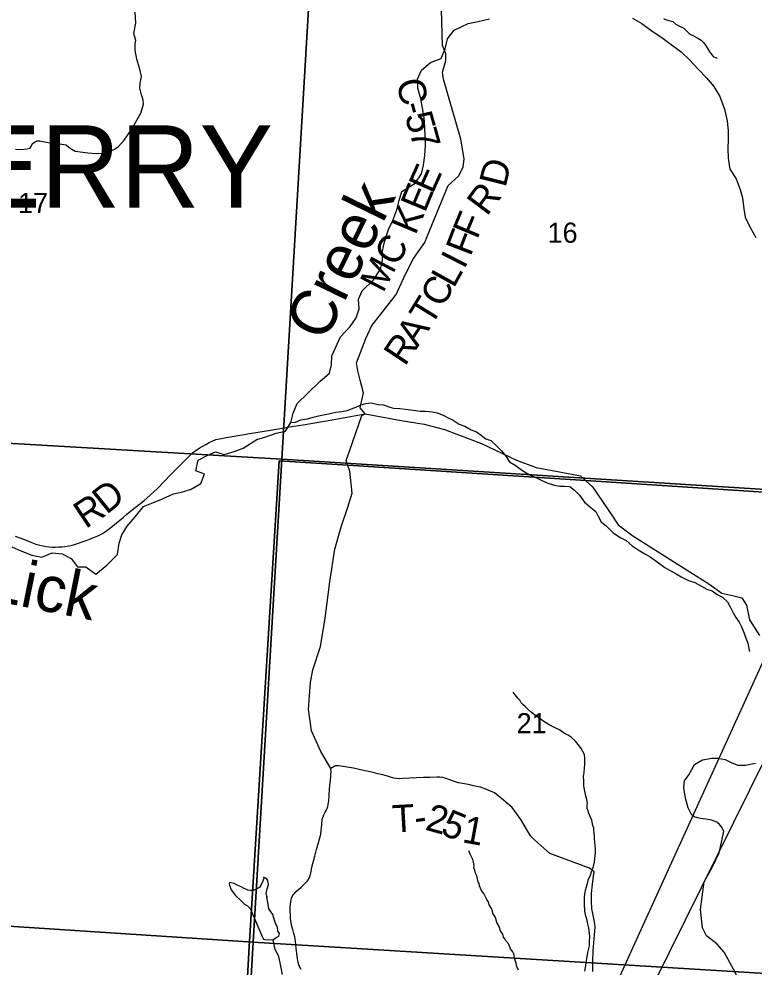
# Model space of a CAD drawing. Extents: x 0 to 45.4, y -2.2 to 22.
# Drawn here: x 4.467 to 5.991, y 17.183 to 19.147 of the extents above; entities that cross this region are included whole.
import ezdxf

# ---------------------------------------------------------------- set-up
doc = ezdxf.new("R2010")
doc.units = 0
for name, color, linetype in [('GM_X_Corporation', 7, 'Continuous'), ('GM_X_County_Road', 7, 'Continuous'), ('GM_X_County_Road_Text', 7, 'Continuous'), ('GM_X_Minor_Lake', 7, 'Continuous'), ('GM_X_Minor_River', 7, 'Continuous'), ('GM_X_Minor_River_Text', 7, 'Continuous'), ('GM_X_Section_Text', 7, 'Continuous'), ('GM_X_Township_Road', 7, 'Continuous'), ('GM_X_Township_Road_Text', 7, 'Continuous'), ('GM_X_Township_Text', 7, 'Continuous'), ('SH_Text', 7, 'Continuous')]:
    doc.layers.add(name, color=color, linetype=linetype)

msp = doc.modelspace()

# ---------------------------------------------------------------- linework, layer by layer
at = {"layer": 'GM_X_Corporation'}
for points in [[(5.073, 19.2613), (5.0121, 18.2353), (3.9206, 18.2985), (3.9891, 19.3268)], [(6.1827, 19.1954), (6.1142, 18.166), (5.0121, 18.2353), (5.073, 19.2613)], [(3.9206, 18.2985), (5.0121, 18.2353), (4.9524, 17.2347), (3.854, 17.3067)], [(5.0121, 18.2353), (6.1142, 18.166), (6.0488, 17.1677), (4.9524, 17.2347)], [(4.9524, 17.2347), (4.8941, 16.2254), (3.7867, 16.2913), (3.854, 17.3067)], [(6.0488, 17.1677), (5.9818, 16.1569), (4.8941, 16.2254), (4.9524, 17.2347)]]:
    msp.add_lwpolyline(points, close=True, dxfattribs=at)
for points in [[(6.1061, 18.1607), (5.642, 18.1908), (5.1488, 18.2228), (5.0067, 18.2321), (4.9442, 17.2251), (4.9098, 16.6105)], [(4.9098, 16.6105), (4.9442, 17.2251), (5.0067, 18.2321), (5.1488, 18.2228), (5.642, 18.1908), (6.1061, 18.1607)]]:
    msp.add_lwpolyline(points, dxfattribs=at)
at = {"layer": 'GM_X_County_Road'}
for points in [[(5.1851, 18.3294), (5.1744, 18.3414), (5.1816, 18.3726), (5.1744, 18.399), (5.1696, 18.4182), (5.1672, 18.435), (5.1864, 18.4854), (5.1984, 18.5118), (5.2176, 18.5357), (5.2488, 18.5765), (5.268, 18.6173), (5.2848, 18.6509), (5.2968, 18.6677), (5.3088, 18.6844), (5.3136, 18.6964), (5.3568, 18.802), (5.3784, 18.8212), (5.3879, 18.8403), (5.3903, 18.8571), (5.3832, 18.8979), (5.3472, 19.0226), (5.3448, 19.037), (5.352, 19.061), (5.352, 19.0754), (5.3448, 19.0921), (5.3422, 19.1916)], [(4.4597, 18.0756), (4.471, 18.0718), (4.4822, 18.0674), (4.4921, 18.063), (4.5019, 18.0589), (4.5108, 18.0569), (4.517, 18.0554), (4.5237, 18.0545), (4.5293, 18.0539), (4.5369, 18.0532), (4.5425, 18.0531), (4.5492, 18.0533), (4.5565, 18.0537), (4.5623, 18.0545), (4.5699, 18.0555), (4.5753, 18.0566), (4.5823, 18.0587), (4.5883, 18.0607), (4.596, 18.0633), (4.6021, 18.0653), (4.6085, 18.0675), (4.6122, 18.069), (4.6202, 18.0721), (4.6306, 18.0767), (4.6403, 18.0812), (4.6469, 18.0854), (4.6541, 18.0908), (4.6652, 18.1001), (4.6831, 18.1146), (4.6908, 18.1213), (4.702, 18.1304), (4.7261, 18.1487), (4.7392, 18.1603), (4.7549, 18.1752), (4.7812, 18.2028), (4.8018, 18.2233), (4.8115, 18.2329), (4.8195, 18.2407), (4.8279, 18.2487), (4.8338, 18.2535), (4.8406, 18.2582), (4.8545, 18.2657), (4.8618, 18.2695), (4.8755, 18.2757), (4.8869, 18.2782), (4.8969, 18.28), (4.9338, 18.2863), (4.9451, 18.2882), (4.9887, 18.2956), (5.0277, 18.3023), (5.0561, 18.3065), (5.1166, 18.3166), (5.1851, 18.3294), (5.2595, 18.3156), (5.3073, 18.3079), (5.3495, 18.2965), (5.426, 18.2677), (5.4988, 18.2333), (5.539, 18.218), (5.6022, 18.2065), (5.6309, 18.2008), (5.6422, 18.1903), (5.6558, 18.1778), (5.6882, 18.1304), (5.6945, 18.1211)], [(5.6945, 18.1211), (5.7094, 18.0993), (5.74, 18.0764), (5.897, 17.9768), (5.9238, 17.9577), (5.9487, 17.952), (5.9659, 17.9481), (5.9755, 17.9328), (5.9812, 17.9022), (6.0023, 17.8696)]]:
    msp.add_lwpolyline(points, dxfattribs=at)
at = {"layer": 'GM_X_Minor_Lake'}
for points in [[(4.9814, 17.328), (4.9795, 17.3348), (4.9818, 17.3451), (4.9844, 17.3538), (4.9829, 17.3625), (4.9803, 17.3663), (4.9739, 17.369), (4.9746, 17.3663), (4.972, 17.3599), (4.9689, 17.3519), (4.9655, 17.3481), (4.9614, 17.3459), (4.953, 17.3417), (4.9462, 17.3413), (4.9413, 17.3425), (4.9391, 17.344), (4.9326, 17.3467), (4.9281, 17.3489), (4.9209, 17.352), (4.913, 17.3558), (4.9073, 17.3577), (4.9035, 17.3581), (4.9028, 17.3554), (4.9039, 17.3524), (4.9069, 17.3433), (4.916, 17.3311), (4.9266, 17.3216), (4.9345, 17.3133), (4.9409, 17.3098), (4.9462, 17.3041), (4.9711, 17.2464), (4.9742, 17.2407), (4.9761, 17.2403), (4.9937, 17.2397)], [(4.9937, 17.2397), (5.0003, 17.2441), (5.0059, 17.2471), (5.0071, 17.2528), (5.004, 17.2574), (5.0033, 17.2657), (4.9999, 17.2722), (4.9965, 17.282), (4.9935, 17.2919), (4.9855, 17.3037), (4.981, 17.3291), (4.9814, 17.328)]]:
    msp.add_lwpolyline(points, dxfattribs=at)
at = {"layer": 'GM_X_Minor_River'}
for points in [[(4.4525, 18.0537), (4.4714, 18.0453), (4.4941, 18.0361), (4.5145, 18.0322), (4.5358, 18.0412), (4.557, 18.0389), (4.5751, 18.0297), (4.5887, 18.0122), (4.6061, 18.0121), (4.6265, 17.9969), (4.6493, 18.0158), (4.6713, 18.0377), (4.6752, 18.0612), (4.6806, 18.0787), (4.6913, 18.0961), (4.708, 18.1158), (4.7255, 18.137), (4.746, 18.1452), (4.765, 18.1528), (4.7877, 18.1633), (4.8067, 18.1678), (4.8241, 18.1731), (4.8439, 18.1851), (4.8515, 18.2041), (4.8341, 18.211), (4.8388, 18.233), (4.857, 18.2428), (4.8744, 18.2503), (4.8926, 18.2449), (4.9131, 18.2509), (4.932, 18.2577), (4.9601, 18.2758), (4.9791, 18.2818), (5.0003, 18.2893), (5.02, 18.2931), (5.0307, 18.3113), (5.0353, 18.3302), (5.0438, 18.3507), (5.0658, 18.3719), (5.0909, 18.3961), (5.1107, 18.4135), (5.1153, 18.4309), (5.1154, 18.4491), (5.1337, 18.4886), (5.1535, 18.5098), (5.1664, 18.5279), (5.1726, 18.5469), (5.1711, 18.5666), (5.1788, 18.5841), (5.2024, 18.6068), (5.2168, 18.6287), (5.2207, 18.6469), (5.2208, 18.6659), (5.2246, 18.6856), (5.2331, 18.7107), (5.2423, 18.7296), (5.2507, 18.7516), (5.2553, 18.7713), (5.2607, 18.7895), (5.2888, 18.8069), (5.3017, 18.8266), (5.3056, 18.844), (5.3087, 18.8645), (5.3096, 18.885), (5.3089, 18.904), (5.3082, 18.9222), (5.3068, 18.9427), (5.3038, 18.9625), (5.3001, 18.9815), (5.2941, 19.0035), (5.2935, 19.0225), (5.3019, 19.0414), (5.3201, 19.0573), (5.3421, 19.0656), (5.3505, 19.0853), (5.3552, 19.1058), (5.3696, 19.124), (5.3985, 19.1375), (5.4189, 19.142), (5.4424, 19.1472)], [(5.7393, 19.1485), (5.7582, 19.1378), (5.7794, 19.1218)], [(5.7794, 19.1218), (5.7998, 19.1088), (5.8194, 19.0944), (5.8398, 19.0791), (5.8571, 19.0623), (5.8745, 19.0441), (5.8926, 19.025), (5.9076, 19.0075), (5.9197, 18.9862), (5.9294, 18.9604), (5.9354, 18.9361), (5.9375, 18.9148), (5.9375, 18.8973), (5.9366, 18.8791), (5.9373, 18.8586), (5.941, 18.8358), (5.9538, 18.816), (5.962, 18.794), (5.9673, 18.7765), (5.9694, 18.7537), (5.9724, 18.7363), (5.9822, 18.7165), (5.9949, 18.6944)], [(5.0307, 18.3113), (5.0402, 18.3121), (5.0512, 18.3166), (5.0652, 18.3189), (5.0769, 18.3223), (5.0879, 18.3253), (5.1019, 18.3276), (5.1121, 18.3295), (5.1238, 18.3325), (5.1367, 18.334), (5.1476, 18.3359), (5.162, 18.3415), (5.1764, 18.3476), (5.1862, 18.3502), (5.1976, 18.3517), (5.2119, 18.3487), (5.2225, 18.3479), (5.2339, 18.3433), (5.2437, 18.3407), (5.2569, 18.3399), (5.2687, 18.3391), (5.2845, 18.3368), (5.2985, 18.3349), (5.3099, 18.3349), (5.3235, 18.3334), (5.3344, 18.3315), (5.3465, 18.3261), (5.3571, 18.3208), (5.3673, 18.3159), (5.3798, 18.3075), (5.3915, 18.3033), (5.4047, 18.2957), (5.4153, 18.2915), (5.4252, 18.2851), (5.435, 18.2771), (5.4452, 18.274), (5.4569, 18.263), (5.4675, 18.2528), (5.4766, 18.2414), (5.4841, 18.23), (5.4958, 18.2231), (5.506, 18.2152), (5.5174, 18.2076), (5.5287, 18.2015), (5.5389, 18.1969), (5.5495, 18.192), (5.5635, 18.1855), (5.5775, 18.1813), (5.5881, 18.179), (5.5983, 18.179), (5.6089, 18.1786), (5.6187, 18.1707), (5.6289, 18.1604), (5.6398, 18.146), (5.6527, 18.135), (5.6629, 18.127), (5.6678, 18.1171), (5.6742, 18.1053), (5.6852, 18.0962), (5.6988, 18.0826), (5.715, 18.0719), (5.726, 18.0666), (5.7385, 18.0559), (5.7509, 18.0472), (5.7645, 18.0388), (5.7755, 18.0331), (5.7929, 18.0202), (5.8061, 18.0111), (5.8159, 18.005), (5.8296, 17.9978), (5.8409, 17.991), (5.8549, 17.9841), (5.8681, 17.9799), (5.8821, 17.9719), (5.8931, 17.9662), (5.9044, 17.9624), (5.9142, 17.9548), (5.9252, 17.9491), (5.9358, 17.9396), (5.9411, 17.929), (5.9479, 17.9172), (5.9531, 17.9074), (5.9603, 17.8975), (5.9648, 17.8876), (5.9698, 17.8759), (5.9739, 17.8641), (5.9781, 17.8542), (5.9799, 17.8432), (5.9818, 17.8371)], [(5.5387, 17.7032), (5.5297, 17.7106), (5.5226, 17.7168), (5.5174, 17.7222), (5.5118, 17.7272), (5.5085, 17.7303), (5.5055, 17.7357), (5.5022, 17.7395), (5.4959, 17.7472), (5.4914, 17.7522)], [(5.64, 17.1744), (5.6425, 17.1865), (5.6426, 17.1926), (5.6434, 17.1967), (5.6459, 17.2085), (5.6464, 17.213), (5.6496, 17.2267), (5.6501, 17.2346), (5.6504, 17.2479), (5.6501, 17.2521), (5.6494, 17.2582), (5.6484, 17.2643), (5.6459, 17.275), (5.6453, 17.2803), (5.6424, 17.2887), (5.6403, 17.2987), (5.6404, 17.3025), (5.6397, 17.3097), (5.6392, 17.3207), (5.6393, 17.3283), (5.641, 17.3382), (5.6418, 17.3423), (5.6434, 17.3492), (5.6463, 17.3586), (5.6471, 17.3632), (5.6518, 17.3737), (5.6542, 17.3805), (5.6582, 17.3915), (5.6586, 17.3949), (5.6603, 17.4009), (5.6616, 17.4138), (5.6621, 17.4188), (5.6626, 17.4267), (5.6616, 17.4351), (5.6606, 17.4416), (5.66, 17.4492), (5.66, 17.4534), (5.6598, 17.4595), (5.6588, 17.4679), (5.6585, 17.4713), (5.657, 17.4762), (5.6553, 17.4835), (5.655, 17.4873), (5.652, 17.4934), (5.648, 17.503), (5.6473, 17.5068), (5.6452, 17.5118), (5.6453, 17.5186), (5.6454, 17.5228), (5.644, 17.5304), (5.6415, 17.54), (5.6412, 17.5438), (5.6387, 17.5545), (5.6384, 17.5583), (5.6378, 17.5647), (5.6378, 17.5689), (5.6376, 17.5784), (5.6381, 17.5818), (5.6385, 17.586), (5.6394, 17.5959), (5.6403, 17.6027), (5.6405, 17.6114), (5.6405, 17.6148), (5.6392, 17.6236), (5.6329, 17.6355), (5.627, 17.6436), (5.6196, 17.6524), (5.6125, 17.6583), (5.6058, 17.6633), (5.5979, 17.6672), (5.5878, 17.6742), (5.5803, 17.6782), (5.5664, 17.6849), (5.5551, 17.6919), (5.5473, 17.697), (5.5387, 17.7032)], [(5.5029, 17.1767), (5.4989, 17.184), (5.4979, 17.1912), (5.495, 17.1992), (5.4929, 17.2103), (5.4911, 17.2145), (5.4863, 17.221), (5.4826, 17.2302), (5.4767, 17.2372), (5.4745, 17.2418), (5.4719, 17.2452), (5.4701, 17.251), (5.4653, 17.2579), (5.4625, 17.2671), (5.4577, 17.2755), (5.4548, 17.2854), (5.4526, 17.2893), (5.4497, 17.2939), (5.4486, 17.2988), (5.4464, 17.3042), (5.442, 17.3119), (5.4399, 17.3188), (5.4373, 17.323), (5.4307, 17.3356), (5.4274, 17.3395), (5.4252, 17.343), (5.4219, 17.3514), (5.4208, 17.3559), (5.4194, 17.3598), (5.4173, 17.3685), (5.4162, 17.372), (5.4136, 17.3774), (5.4122, 17.3838), (5.4104, 17.3884), (5.4105, 17.3926), (5.4095, 17.4006), (5.4077, 17.4056), (5.4022, 17.4167), (5.3997, 17.424)], [(4.9937, 17.2397), (4.9967, 17.2222), (5.0049, 17.2047), (5.0094, 17.1849), (5.0131, 17.1674)]]:
    msp.add_lwpolyline(points, dxfattribs=at)
at = {"layer": 'GM_X_Township_Road'}
for points in [[(4.46, 18.8772), (4.471, 18.8769), (4.4839, 18.8783), (4.4902, 18.8798), (4.4927, 18.8831), (4.4953, 18.889), (4.5005, 18.8923), (4.5053, 18.8946), (4.5108, 18.8946), (4.5311, 18.8905), (4.5513, 18.8883), (4.565, 18.8864), (4.5709, 18.8817), (4.5768, 18.8772), (4.5837, 18.8736), (4.6099, 18.8699), (4.6272, 18.8684), (4.6398, 18.8691), (4.6534, 18.8717), (4.6655, 18.8776), (4.6733, 18.8831), (4.6851, 18.8964), (4.7002, 18.9181), (4.7197, 18.9517), (4.7252, 18.9705), (4.7245, 18.9786), (4.7212, 18.99), (4.7179, 19.0036), (4.7186, 19.0139), (4.7212, 19.0279), (4.7179, 19.0434), (4.7116, 19.0637), (4.7079, 19.0825), (4.7079, 19.0965), (4.7094, 19.1024), (4.705, 19.1171), (4.7094, 19.1385), (4.7079, 19.1613)], [(5.8029, 19.1482), (5.8075, 19.1458), (5.8142, 19.1442), (5.8226, 19.1416), (5.829, 19.1366), (5.8349, 19.1326), (5.8452, 19.1278), (5.8572, 19.1166), (5.8643, 19.1129), (5.8741, 19.1071), (5.8813, 19.103), (5.8868, 19.098), (5.8915, 19.0907), (5.8961, 19.0837), (5.8995, 19.0786), (5.9031, 19.0731), (5.9072, 19.0689), (5.9114, 19.0671), (5.9147, 19.066)], [(5.1523, 18.2521), (5.1778, 18.3257), (5.1851, 18.3294)], [(5.1136, 17.5943), (5.0929, 17.6297), (5.0739, 17.6726), (5.0675, 17.7171), (5.0717, 17.7725), (5.0762, 17.7987), (5.0925, 17.8469), (5.102, 17.9058), (5.1119, 17.981), (5.1217, 18.0485), (5.1354, 18.0952), (5.1486, 18.1357), (5.1578, 18.1645), (5.1532, 18.2103), (5.149, 18.2223), (5.1455, 18.2323), (5.1523, 18.2521)], [(5.5353, 17.4473), (5.5274, 17.4551), (5.5075, 17.4887), (5.4898, 17.5133), (5.4718, 17.5286), (5.4526, 17.544), (5.4316, 17.5531), (5.4239, 17.5554), (5.4159, 17.5571), (5.4092, 17.5584), (5.4018, 17.5602), (5.3907, 17.5627), (5.3782, 17.565), (5.3682, 17.5678), (5.358, 17.5718), (5.3505, 17.5742), (5.3459, 17.5755), (5.3394, 17.5761), (5.3331, 17.5762), (5.3189, 17.5755), (5.3056, 17.5756), (5.2903, 17.5753), (5.2631, 17.5739), (5.2556, 17.5731), (5.2496, 17.5736), (5.2446, 17.5743), (5.2373, 17.5763), (5.2308, 17.5782), (5.2214, 17.5811), (5.2112, 17.5836), (5.2016, 17.586), (5.1917, 17.5884), (5.1755, 17.5919), (5.1607, 17.5948), (5.1391, 17.5988), (5.1296, 17.6002), (5.1263, 17.6002), (5.1232, 17.5997), (5.1207, 17.5986), (5.1173, 17.5963), (5.1136, 17.5943)], [(5.9185, 17.4197), (5.925, 17.4482), (5.9282, 17.4646), (5.9236, 17.4733), (5.9195, 17.4786), (5.9135, 17.4832), (5.9026, 17.4873), (5.8913, 17.4897), (5.8802, 17.4909), (5.8734, 17.4924), (5.8669, 17.4943), (5.8611, 17.4991), (5.8546, 17.5126), (5.8498, 17.5305), (5.846, 17.5495), (5.8455, 17.5555), (5.8469, 17.5688), (5.8559, 17.5812), (5.8619, 17.5922), (5.8674, 17.6026), (5.8843, 17.6121), (5.9032, 17.6161), (5.9161, 17.6161), (5.9311, 17.6131), (5.945, 17.6061), (5.957, 17.6016), (5.9729, 17.6011), (5.9938, 17.6056)], [(5.0394, 17.2414), (5.0388, 17.2459), (5.0369, 17.2526), (5.0346, 17.2608), (5.0323, 17.2696), (5.0315, 17.2758), (5.0303, 17.2831), (5.03, 17.2892), (5.0296, 17.301), (5.0296, 17.3074), (5.03, 17.3132), (5.0305, 17.3185), (5.0315, 17.3228), (5.0323, 17.3257), (5.0334, 17.3295), (5.0353, 17.3324), (5.0376, 17.3348), (5.0421, 17.3393), (5.0519, 17.3488), (5.0569, 17.3532), (5.0601, 17.3563), (5.0654, 17.3616), (5.0674, 17.3642), (5.0684, 17.3662), (5.0695, 17.3686), (5.0707, 17.372), (5.0719, 17.3781), (5.0741, 17.3897), (5.0782, 17.4049), (5.0804, 17.4126), (5.0843, 17.4264), (5.0885, 17.4432), (5.0926, 17.4586), (5.0937, 17.4661), (5.0945, 17.4726), (5.0949, 17.4773), (5.0953, 17.4821), (5.0957, 17.4863), (5.096, 17.4891), (5.0966, 17.4916), (5.0976, 17.4945), (5.0991, 17.4984), (5.1017, 17.5036), (5.1039, 17.5076), (5.1058, 17.5116), (5.1072, 17.5154), (5.108, 17.5199), (5.1093, 17.5279), (5.1103, 17.5377), (5.1112, 17.5525), (5.1114, 17.5583), (5.1135, 17.5774), (5.1139, 17.5826), (5.1141, 17.5861), (5.1136, 17.5943)], [(5.6593, 17.3806), (5.6547, 17.3846), (5.6501, 17.3879), (5.5676, 17.4181), (5.5426, 17.4401), (5.5353, 17.4473)], [(5.9292, 17.214), (5.9136, 17.2312), (5.8923, 17.2476), (5.8841, 17.264), (5.88, 17.3025), (5.8874, 17.3599), (5.9046, 17.391), (5.9185, 17.4197)], [(5.6565, 17.1741), (5.6568, 17.1939), (5.6573, 17.2175), (5.658, 17.2248), (5.6601, 17.2497), (5.6615, 17.2656), (5.6601, 17.2769), (5.6589, 17.2838), (5.6568, 17.2943), (5.6545, 17.3036), (5.6542, 17.3203), (5.6543, 17.3345), (5.6553, 17.3483), (5.658, 17.371), (5.6593, 17.3806)], [(5.0519, 17.1778), (5.0482, 17.1853), (5.0461, 17.1928), (5.0446, 17.2009), (5.0435, 17.2108), (5.042, 17.2222), (5.0402, 17.2359), (5.0394, 17.2414)], [(5.9918, 16.9998), (5.9809, 17.0373), (5.9754, 17.0602), (5.9662, 17.0757), (5.9662, 17.084), (5.9662, 17.0958), (5.9681, 17.1196), (5.9626, 17.1434), (5.9525, 17.1708), (5.9292, 17.214)]]:
    msp.add_lwpolyline(points, dxfattribs=at)
at = {"layer": 'SH_Text'}
msp.add_lwpolyline([(7.4129, 20.9), (4.8173, 15.1976), (7.4129, 20.4406)], close=True, dxfattribs=at)

# ---------------------------------------------------------------- texts
at = {"layer": 'GM_X_County_Road_Text'}
for s, rotation, p in [('C', 283.0308, (5.2489, 19.0175)), ('5', 285.9904, (5.2666, 18.9464)), ('-', 286.0474, (5.2602, 18.9689)), ('7', 285.6604, (5.2763, 18.9129)), ('D', 75.9454, (5.4756, 18.7964)), ('E', 65.8064, (5.3247, 18.7829)), ('E', 67.5026, (5.3087, 18.744)), ('R', 53.1987, (5.4371, 18.7369)), ('K', 67.1785, (5.2891, 18.6976)), ('F', 67.4881, (5.4169, 18.6889)), ('C', 60.4093, (5.2501, 18.6321)), ('F', 68.855, (5.4032, 18.6535)), ('I', 63.0784, (5.3901, 18.627)), ('M', 62.4774, (5.2218, 18.5779)), ('L', 60.9576, (5.3684, 18.5878)), ('C', 60.4905, (5.3451, 18.5467)), ('T', 58.2888, (5.3216, 18.5085)), ('A', 56.779, (5.2933, 18.4653)), ('R', 56.2249, (5.267, 18.426)), ('D', 39.1121, (4.6487, 18.1192)), ('R', 33.8016, (4.6054, 18.0899))]:
    msp.add_text(s, height=0.0568, rotation=rotation, dxfattribs=at).set_placement(p)
at = {"layer": 'GM_X_Minor_River_Text'}
for s, height, rotation, p in [('Creek', 0.09468, 64.0091, (5.1009, 18.4753)), ('Lick', 0.0947, 348.6135, (4.3978, 17.9454))]:
    msp.add_text(s, height=height, rotation=rotation, dxfattribs=at).set_placement(p)
at = {"layer": 'GM_X_Section_Text'}
for s, p in [('17', (4.4654, 18.7449)), ('16', (5.5629, 18.6835)), ('21', (5.4988, 17.6672))]:
    msp.add_text(s, height=0.04186, rotation=0, dxfattribs=at).set_placement(p)
at = {"layer": 'GM_X_Township_Road_Text'}
for s, rotation, p in [('T', 3.2256, (5.2425, 17.4615)), ('2', 344.6074, (5.3071, 17.468)), ('5', 337.0855, (5.3389, 17.4594)), ('-', 7.9157, (5.29, 17.4644)), ('1', 349.6165, (5.3841, 17.4419))]:
    msp.add_text(s, height=0.0568, rotation=rotation, dxfattribs=at).set_placement(p)
at = {"layer": 'GM_X_Township_Text'}
msp.add_text('PERRY', height=0.17045, rotation=0, dxfattribs=at).set_placement((4.2084, 18.7563))

doc.saveas('drawing.dxf')
